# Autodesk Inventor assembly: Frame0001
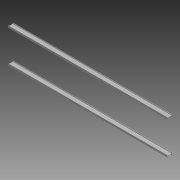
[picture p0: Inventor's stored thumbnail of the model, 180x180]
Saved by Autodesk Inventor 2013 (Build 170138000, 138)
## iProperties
Created: 2009-11
Part Number: Frame0001
Document SubType Name: Assembly
Designer: pokornp
_FrameDoc: Frame Assembly
_Version: 15.0.0
Author: pokornp
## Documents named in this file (4)
- C:\Users\boganb\Documents\B2 Design\Goodyear\2013 Tutorial Files\Frame Analysis 1\asm\Frame\Frame0001.iam
- C:\Users\boganb\Documents\B2 Design\Goodyear\2013 Tutorial Files\Frame Analysis 1\asm\Frame\Skeleton0001.ipt
- C:\Users\boganb\Documents\B2 Design\Goodyear\2013 Tutorial Files\Frame Analysis 1\asm\Frame\DIN I 300 00000001.ipt
- C:\Users\boganb\Documents\B2 Design\Goodyear\2013 Tutorial Files\Frame Analysis 1\asm\Frame\DIN I 300 00000002.ipt
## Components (3 placed, 3 different names)
1. Frame Reference Model
2. DIN I 300 00000001:1
3. DIN I 300 00000002:1
